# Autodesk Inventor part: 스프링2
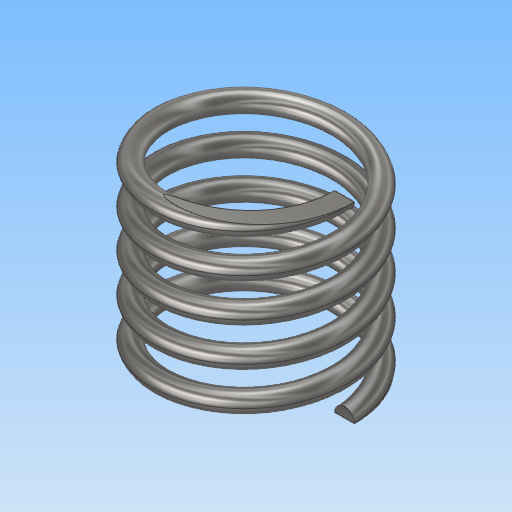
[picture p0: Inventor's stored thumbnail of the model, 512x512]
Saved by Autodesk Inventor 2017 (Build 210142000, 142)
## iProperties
Part Number: 스프링2
Material: 스테인레스 스틸
Document SubType Name: Modeling
Designer: MRC
Density: 8 g/cm^3
Appearance: 반연마
Mass: 6.9526 g
Surface Area: 17.6927 cm^2
Volume: 0.869075 cm^3
Author: MRC
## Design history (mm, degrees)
sketch "스케치1"
  geometry: L1 (0, 0)-(0, 19.5); L2 (0, 19.5)-(9, 19.5); L3 (0, 0)-(9, 0); C1 r 1 at (9, 0); 1 further point
  constraints: 6 end point, 2 coincident, 2 horizontal, 1 centre point, 1 vertical
  dimensions: "d0" = 19.5 distance of L1.start L1.end (derived); "d1" = 9 distance of L1.end L2.end; "d2" = 9 distance of L1.start L3.end; "d3" = 2 diameter of C1
feature "코일1" sketch "스케치1" pitch "d4" = 10; turns "d6" = 5; dims "d5" = 19.5 (= d0), "d7" = 0, angle "d8" = 90 deg, angle "d9" = 90 deg, "d10" = 0, "d11" = 0
sketch "스케치2"
  geometry: L1 (19.5, 15)-(0, 15); L2 (0, 15)-(0, -15); L3 (0, -15)-(19.5, -15); L4 (19.5, -15)-(19.5, 15); 2 further points
  constraints: 8 end point, 2 parallel, 1 coincident, 1 horizontal, 1 midpoint, 1 perpendicular
  dimensions: "d12" = 19.5 distance of L2.end L3.end (= d0); "d13" = 30 distance of L3.end L1.start
extrude "돌출1" sketch "스케치2" stored distance "d14" = 0; taper "d15" = 0 deg
node "솔리드1"
